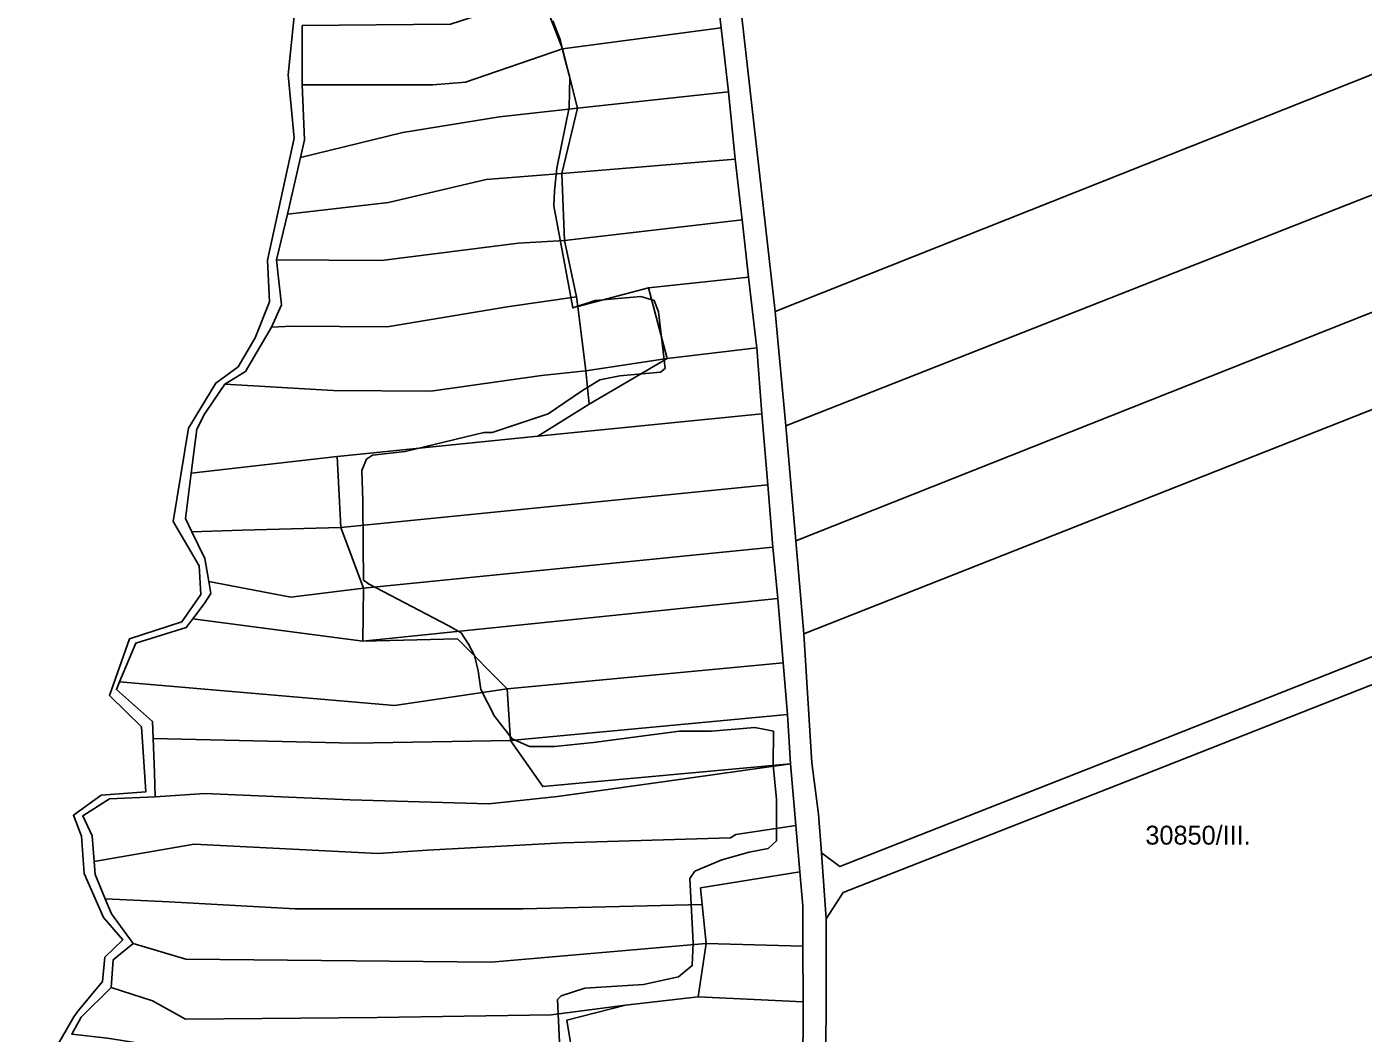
# Model space of a CAD drawing. Extents: x -541351 to -537540, y -1162694 to -1159725.
# Drawn here: x -540941.8 to -540588.2, y -1160827.9 to -1160561.6 of the extents above; entities that cross this region are included whole.
import ezdxf

# ---------------------------------------------------------------- set-up
doc = ezdxf.new("R2010")
doc.units = 0
for name, color, linetype in [('95560013', 7, 'Continuous'), ('95610013', 7, 'Continuous'), ('95620013', 7, 'Continuous'), ('95630013', 7, 'Continuous'), ('95640013', 7, 'Continuous'), ('95660013', 7, 'Continuous')]:
    doc.layers.add(name, color=color, linetype=linetype)

msp = doc.modelspace()

# ---------------------------------------------------------------- linework, layer by layer
at = {"layer": '95560013'}
for points in [[(-540743.76, -1160636.96), (-540754.11, -1160545.74), (-540579.05, -1160495.45), (-540572.28, -1160568.88)], [(-540572.28, -1160568.88), (-540569.38, -1160599.67), (-540740.93, -1160667.18), (-540743.11, -1160643.61), (-540743.76, -1160636.96)], [(-540738.26, -1160697.63), (-540740.93, -1160667.18), (-540569.38, -1160599.67), (-540569.2, -1160602.34), (-540566.45, -1160629.45)], [(-540566.45, -1160629.45), (-540564.11, -1160654.29), (-540736.17, -1160722.24), (-540738.26, -1160697.63)], [(-540562.94, -1160719.19), (-540648.19, -1160752.95), (-540726.69, -1160783.83), (-540731.48, -1160780.22), (-540732.29, -1160769.97), (-540734.07, -1160756.37), (-540736.17, -1160722.24), (-540564.11, -1160654.29), (-540562.24, -1160676.31), (-540558.93, -1160712.51)], [(-540725.79, -1160790.64), (-540730.27, -1160797.63), (-540731.48, -1160780.22), (-540726.69, -1160783.83), (-540648.19, -1160752.95), (-540562.94, -1160719.19), (-540558.93, -1160712.51), (-540557.55, -1160724.92), (-540557.36, -1160729.42), (-540562.42, -1160726.46), (-540646.61, -1160759.66)], [(-540547.74, -1160834.19), (-540730.09, -1160905.46), (-540730.34, -1160853.99), (-540730.27, -1160797.63), (-540725.79, -1160790.64), (-540646.61, -1160759.66), (-540562.42, -1160726.46), (-540557.36, -1160729.42), (-540550.62, -1160801.05)]]:
    msp.add_lwpolyline(points, close=True, dxfattribs=at)
at = {"layer": '95610013'}
for points in [[(-540805.57, -1160553.03), (-540808.15, -1160547.85), (-540760.46, -1160541.6), (-540758.03, -1160561.9), (-540800, -1160567.48)], [(-540800, -1160567.48), (-540758.03, -1160561.9), (-540756.15, -1160578.85), (-540796.08, -1160583.18)], [(-540796.08, -1160583.18), (-540756.15, -1160578.85), (-540754.35, -1160596.66), (-540800.21, -1160600.46)], [(-540754.35, -1160596.66), (-540752.47, -1160612.65), (-540799.49, -1160618.19), (-540800.21, -1160600.46)], [(-540796.31, -1160633.04), (-540799.49, -1160618.19), (-540752.47, -1160612.65), (-540750.86, -1160627.86), (-540777.31, -1160630.72), (-540795.98, -1160635.63)], [(-540748.98, -1160643.75), (-540748.58, -1160646.52), (-540772.38, -1160649.35), (-540777.31, -1160630.72), (-540750.86, -1160627.86)], [(-540795.98, -1160635.63), (-540777.31, -1160630.72), (-540772.38, -1160649.35), (-540793.84, -1160652.65)], [(-540806.57, -1160669.96), (-540792.94, -1160661.5), (-540772.38, -1160649.35), (-540748.58, -1160646.52), (-540747.32, -1160663.98)], [(-540793.84, -1160652.65), (-540772.38, -1160649.35), (-540792.94, -1160661.5)], [(-540747.32, -1160663.98), (-540745.69, -1160682.81), (-540858.65, -1160694.1), (-540859.62, -1160675.32), (-540806.57, -1160669.96)], [(-540745.69, -1160682.81), (-540744.39, -1160699.26), (-540852.69, -1160710.11), (-540858.65, -1160694.1)], [(-540743.07, -1160712.89), (-540852.85, -1160724.16), (-540852.69, -1160710.11), (-540744.39, -1160699.26)], [(-540827.83, -1160723.53), (-540852.85, -1160724.16), (-540743.07, -1160712.89), (-540741.64, -1160729.93), (-540814.64, -1160736.75)], [(-540740.47, -1160743.58), (-540813.8, -1160750.47), (-540814.64, -1160736.75), (-540741.64, -1160729.93)], [(-540739.73, -1160756.66), (-540805.25, -1160762.67), (-540813.8, -1160750.47), (-540740.47, -1160743.58)], [(-540798.89, -1160824.47), (-540783.37, -1160820.48), (-540764.18, -1160818.28), (-540736.36, -1160819.57), (-540736.43, -1160839.07), (-540797, -1160835.7)]]:
    msp.add_lwpolyline(points, close=True, dxfattribs=at)
at = {"layer": '95620013'}
for points in [[(-540829.71, -1160560.88), (-540805.57, -1160553.03), (-540800, -1160567.48), (-540825.69, -1160576.28), (-540834.33, -1160576.93), (-540868.91, -1160576.98), (-540868.91, -1160561.29)], [(-540796.08, -1160583.18), (-540816.71, -1160585.45), (-540842.29, -1160589.58), (-540869.32, -1160596.18), (-540868.34, -1160591.53), (-540868.91, -1160576.98), (-540834.33, -1160576.93), (-540825.69, -1160576.28), (-540800, -1160567.48)], [(-540869.32, -1160596.18), (-540842.29, -1160589.58), (-540816.71, -1160585.45), (-540796.08, -1160583.18), (-540800.21, -1160600.46), (-540820.2, -1160601.98), (-540846.1, -1160608.14), (-540872.83, -1160611.2)], [(-540799.49, -1160618.19), (-540811.69, -1160618.87), (-540847.93, -1160623.45), (-540875.72, -1160623.23), (-540872.83, -1160611.2), (-540846.1, -1160608.14), (-540820.2, -1160601.98), (-540800.21, -1160600.46)], [(-540799.49, -1160618.19), (-540796.31, -1160633.04), (-540814.68, -1160635.72), (-540846.44, -1160641.04), (-540871.61, -1160640.84), (-540876.99, -1160641.09), (-540874.38, -1160635.18), (-540875.26, -1160627.34), (-540875.72, -1160623.23), (-540847.93, -1160623.45), (-540811.69, -1160618.87)], [(-540846.44, -1160641.04), (-540814.68, -1160635.72), (-540796.31, -1160633.04), (-540795.98, -1160635.63), (-540793.84, -1160652.65), (-540805.6, -1160653.89), (-540834.9, -1160658.02), (-540860.69, -1160657.81), (-540889.37, -1160656.16), (-540883.87, -1160652.81), (-540876.99, -1160641.09), (-540871.61, -1160640.84)], [(-540889.37, -1160656.16), (-540860.69, -1160657.81), (-540834.9, -1160658.02), (-540805.6, -1160653.89), (-540793.84, -1160652.65), (-540792.94, -1160661.5), (-540806.57, -1160669.96), (-540859.62, -1160675.32), (-540885.15, -1160678.24), (-540898.27, -1160679.74), (-540896.82, -1160668.04), (-540894.64, -1160663.92), (-540894.25, -1160663.31)], [(-540884.83, -1160694.83), (-540898.07, -1160695.2), (-540899.76, -1160691.7), (-540898.27, -1160679.74), (-540885.15, -1160678.24), (-540859.62, -1160675.32), (-540858.65, -1160694.1)], [(-540884.83, -1160694.83), (-540858.65, -1160694.1), (-540852.69, -1160710.11), (-540871.87, -1160712.51), (-540893.63, -1160708.4), (-540894.63, -1160702.3), (-540898.07, -1160695.2)], [(-540893.63, -1160708.4), (-540871.87, -1160712.51), (-540852.69, -1160710.11), (-540852.85, -1160724.16), (-540897.87, -1160718.26), (-540894.88, -1160714.31), (-540893.12, -1160711.56)], [(-540912.96, -1160724.74), (-540899.59, -1160720.53), (-540897.87, -1160718.26), (-540852.85, -1160724.16), (-540827.83, -1160723.53), (-540814.64, -1160736.75), (-540844.5, -1160741.17), (-540917.21, -1160734.89)], [(-540908.49, -1160745.39), (-540918.08, -1160736.97), (-540917.21, -1160734.89), (-540844.5, -1160741.17), (-540814.64, -1160736.75), (-540813.8, -1160750.47), (-540855.26, -1160751.17), (-540908.32, -1160749.94)], [(-540819.51, -1160767.18), (-540856.22, -1160766.12), (-540894.69, -1160764.48), (-540907.82, -1160765.33), (-540907.99, -1160759.02), (-540908.32, -1160749.94), (-540855.26, -1160751.17), (-540813.8, -1160750.47), (-540805.25, -1160762.67), (-540739.73, -1160756.66), (-540772.26, -1160761.2), (-540801.38, -1160765.27)], [(-540754.15, -1160775.29), (-540755.58, -1160776.25), (-540799.95, -1160777.52), (-540835.73, -1160779.43), (-540848.93, -1160780.39), (-540897.45, -1160777.89), (-540923.95, -1160782.5), (-540924.46, -1160775.65), (-540926.98, -1160770.35), (-540919.91, -1160765.89), (-540907.82, -1160765.33), (-540894.69, -1160764.48), (-540856.22, -1160766.12), (-540819.51, -1160767.18), (-540801.38, -1160765.27), (-540772.26, -1160761.2), (-540739.73, -1160756.66), (-540738.29, -1160772.93)], [(-540897.45, -1160777.89), (-540848.93, -1160780.39), (-540835.73, -1160779.43), (-540799.95, -1160777.52), (-540755.58, -1160776.25), (-540754.15, -1160775.29), (-540738.29, -1160772.93), (-540737.2, -1160785.2), (-540763.52, -1160789.41), (-540763.07, -1160793.88), (-540810.44, -1160795.03), (-540870.75, -1160794.98), (-540904.1, -1160793.14), (-540921, -1160792.33), (-540923.7, -1160785.88), (-540923.95, -1160782.5)], [(-540763.07, -1160793.88), (-540763.52, -1160789.41), (-540737.2, -1160785.2), (-540736.46, -1160794.17), (-540736.47, -1160804.87), (-540762.03, -1160804.16)], [(-540913.61, -1160804.14), (-540919.33, -1160796.31), (-540921, -1160792.33), (-540904.1, -1160793.14), (-540870.75, -1160794.98), (-540810.44, -1160795.03), (-540763.07, -1160793.88), (-540762.03, -1160804.16), (-540818.88, -1160809.11), (-540899.7, -1160808.29)], [(-540762.03, -1160804.16), (-540764.18, -1160818.28), (-540783.37, -1160820.48), (-540803, -1160823.08), (-540849.08, -1160823.76), (-540899.74, -1160824.18), (-540908.47, -1160819.38), (-540919.49, -1160815.78), (-540918.9, -1160808.46), (-540913.61, -1160804.14), (-540899.7, -1160808.29), (-540818.88, -1160809.11)], [(-540762.03, -1160804.16), (-540736.47, -1160804.87), (-540736.36, -1160819.57), (-540764.18, -1160818.28)], [(-540838.25, -1160836.9), (-540876.25, -1160836.44), (-540903.88, -1160831.84), (-540920.43, -1160829.18), (-540929.88, -1160828.15), (-540927.39, -1160823.69), (-540919.49, -1160815.78), (-540908.47, -1160819.38), (-540899.74, -1160824.18), (-540849.08, -1160823.76), (-540803, -1160823.08), (-540783.37, -1160820.48), (-540798.89, -1160824.47), (-540797, -1160835.7), (-540822.78, -1160836.73)]]:
    msp.add_lwpolyline(points, close=True, dxfattribs=at)
at = {"layer": '95630013'}
for points in [[(-540941.79, -1160845.2), (-540929.37, -1160823.59), (-540928.15, -1160822.01), (-540921.76, -1160814.24), (-540921.1, -1160807.76), (-540916.4, -1160803.22), (-540921.47, -1160797.25), (-540926.57, -1160785.66), (-540927.28, -1160775.78), (-540929.44, -1160770.22), (-540922.07, -1160764.9), (-540910.26, -1160764.01), (-540911.42, -1160746.8), (-540919.92, -1160738.52), (-540914.63, -1160723.57), (-540900.76, -1160719.02), (-540895.75, -1160711.83), (-540896.14, -1160704.26), (-540903.05, -1160692.48), (-540899.02, -1160667.81), (-540891.8, -1160655.88), (-540885.88, -1160651.59), (-540881.31, -1160643.94), (-540877.54, -1160634.39), (-540878.1, -1160623.35), (-540871.02, -1160591.04), (-540872.59, -1160574.32), (-540870.95, -1160557.89)], [(-540868.91, -1160561.29), (-540868.91, -1160576.98), (-540868.34, -1160591.53), (-540869.32, -1160596.18), (-540872.83, -1160611.2), (-540875.72, -1160623.23), (-540875.26, -1160627.34), (-540874.38, -1160635.18), (-540876.99, -1160641.09), (-540883.87, -1160652.81), (-540889.37, -1160656.16), (-540894.25, -1160663.31), (-540894.64, -1160663.92), (-540896.82, -1160668.04), (-540898.27, -1160679.74), (-540899.76, -1160691.7), (-540898.07, -1160695.2), (-540894.63, -1160702.3), (-540893.63, -1160708.4), (-540893.12, -1160711.56), (-540894.88, -1160714.31), (-540897.87, -1160718.26), (-540899.59, -1160720.53), (-540912.96, -1160724.74), (-540917.21, -1160734.89), (-540918.08, -1160736.97), (-540908.49, -1160745.39), (-540908.32, -1160749.94), (-540907.99, -1160759.02), (-540907.82, -1160765.33), (-540919.91, -1160765.89), (-540926.98, -1160770.35), (-540924.46, -1160775.65), (-540923.95, -1160782.5), (-540923.7, -1160785.88), (-540921, -1160792.33), (-540919.33, -1160796.31), (-540913.61, -1160804.14), (-540918.9, -1160808.46), (-540919.49, -1160815.78), (-540927.39, -1160823.69), (-540929.88, -1160828.15)]]:
    msp.add_lwpolyline(points, dxfattribs=at)
at = {"layer": '95640013'}
for points in [[(-540736.43, -1160839.07), (-540736.36, -1160819.57), (-540736.47, -1160804.87), (-540736.46, -1160794.17), (-540737.2, -1160785.2), (-540738.29, -1160772.93), (-540739.73, -1160756.66), (-540740.47, -1160743.58), (-540741.64, -1160729.93), (-540743.07, -1160712.89), (-540744.39, -1160699.26), (-540745.69, -1160682.81), (-540747.32, -1160663.98), (-540748.58, -1160646.52), (-540748.98, -1160643.75), (-540750.86, -1160627.86), (-540752.47, -1160612.65), (-540754.35, -1160596.66), (-540756.15, -1160578.85), (-540758.03, -1160561.9), (-540760.46, -1160541.6)], [(-540754.11, -1160545.74), (-540743.76, -1160636.96), (-540743.11, -1160643.61), (-540740.93, -1160667.18), (-540738.26, -1160697.63), (-540736.17, -1160722.24), (-540734.07, -1160756.37), (-540732.29, -1160769.97), (-540731.48, -1160780.22), (-540730.27, -1160797.63), (-540730.34, -1160853.99)]]:
    msp.add_lwpolyline(points, dxfattribs=at)
at = {"layer": '95660013'}
for points in [[(-540939.38, -1160841), (-540929.37, -1160823.59), (-540928.15, -1160822.01), (-540921.76, -1160814.24), (-540921.1, -1160807.76), (-540916.4, -1160803.22), (-540921.47, -1160797.25), (-540926.57, -1160785.66), (-540927.28, -1160775.78), (-540929.44, -1160770.22), (-540922.07, -1160764.9), (-540910.26, -1160764.01), (-540911.42, -1160746.8), (-540919.92, -1160738.52), (-540914.63, -1160723.57), (-540900.76, -1160719.02), (-540895.75, -1160711.83), (-540896.14, -1160704.26), (-540903.05, -1160692.48), (-540899.02, -1160667.81), (-540891.8, -1160655.88), (-540885.88, -1160651.59), (-540881.31, -1160643.94), (-540877.54, -1160634.39), (-540878.1, -1160623.35), (-540871.02, -1160591.04), (-540872.59, -1160574.32), (-540870.95, -1160557.89)], [(-540799.87, -1160851), (-540801.37, -1160819), (-540800.37, -1160818), (-540794.12, -1160816), (-540778.62, -1160815), (-540769.37, -1160813), (-540765.69, -1160810), (-540765.5, -1160804), (-540766.37, -1160787), (-540765, -1160785), (-540757.87, -1160782), (-540750.62, -1160780), (-540745.62, -1160779), (-540743.37, -1160777), (-540743.37, -1160766), (-540744.31, -1160757), (-540744.19, -1160748), (-540746.38, -1160747.56), (-540749.12, -1160747), (-540760.62, -1160748), (-540769.12, -1160748), (-540784.5, -1160750), (-540791.81, -1160751), (-540802.19, -1160752), (-540808.81, -1160752), (-540813.37, -1160750), (-540818, -1160744), (-540821.62, -1160737), (-540822.31, -1160732), (-540823.31, -1160728), (-540824.87, -1160725), (-540826.87, -1160722), (-540830.31, -1160720), (-540851.37, -1160709), (-540852.1, -1160708.44), (-540852.69, -1160708), (-540852.77, -1160698.67), (-540852.87, -1160687), (-540853.12, -1160679), (-540851.87, -1160676), (-540850.31, -1160675), (-540841.69, -1160674), (-540820.87, -1160669), (-540818.62, -1160669), (-540803.81, -1160664), (-540795, -1160658), (-540790.12, -1160655), (-540784.87, -1160654), (-540774.12, -1160653), (-540772.87, -1160652), (-540774.62, -1160637), (-540775.81, -1160634), (-540779.31, -1160633), (-540791.37, -1160634), (-540797.31, -1160636), (-540802.31, -1160609), (-540802.19, -1160605), (-540801.5, -1160599), (-540798.31, -1160583), (-540798.12, -1160575), (-540799.55, -1160569.44), (-540800.69, -1160565), (-540801.55, -1160562.78), (-540802.62, -1160560)], [(-540802.62, -1160560), (-540801.55, -1160562.78), (-540800.69, -1160565), (-540799.55, -1160569.44), (-540798.12, -1160575), (-540798.31, -1160583), (-540801.5, -1160599), (-540802.19, -1160605), (-540802.31, -1160609), (-540797.31, -1160636), (-540791.37, -1160634), (-540779.31, -1160633), (-540775.81, -1160634), (-540774.62, -1160637), (-540772.87, -1160652), (-540774.12, -1160653), (-540784.87, -1160654), (-540790.12, -1160655), (-540795, -1160658), (-540803.81, -1160664), (-540818.62, -1160669), (-540820.87, -1160669), (-540841.69, -1160674), (-540850.31, -1160675), (-540851.87, -1160676), (-540853.12, -1160679), (-540852.87, -1160687), (-540852.77, -1160698.67), (-540852.69, -1160708), (-540852.1, -1160708.44), (-540851.37, -1160709), (-540830.31, -1160720), (-540826.87, -1160722), (-540824.87, -1160725), (-540823.31, -1160728), (-540822.31, -1160732), (-540821.62, -1160737), (-540818, -1160744), (-540813.37, -1160750), (-540808.81, -1160752), (-540802.19, -1160752), (-540791.81, -1160751), (-540784.5, -1160750), (-540769.12, -1160748), (-540760.62, -1160748), (-540749.12, -1160747), (-540746.38, -1160747.56), (-540744.19, -1160748), (-540744.31, -1160757), (-540743.37, -1160766), (-540743.37, -1160777), (-540745.62, -1160779), (-540750.62, -1160780), (-540757.87, -1160782), (-540765, -1160785), (-540766.37, -1160787), (-540765.5, -1160804), (-540765.69, -1160810), (-540769.37, -1160813), (-540778.62, -1160815), (-540794.12, -1160816), (-540800.37, -1160818), (-540801.37, -1160819), (-540799.87, -1160851)]]:
    msp.add_lwpolyline(points, dxfattribs=at)

# ---------------------------------------------------------------- texts
msp.add_text('30850/III.', height=5, rotation=0, dxfattribs=at).set_placement((-540645.81, -1160778))

doc.saveas('drawing.dxf')
